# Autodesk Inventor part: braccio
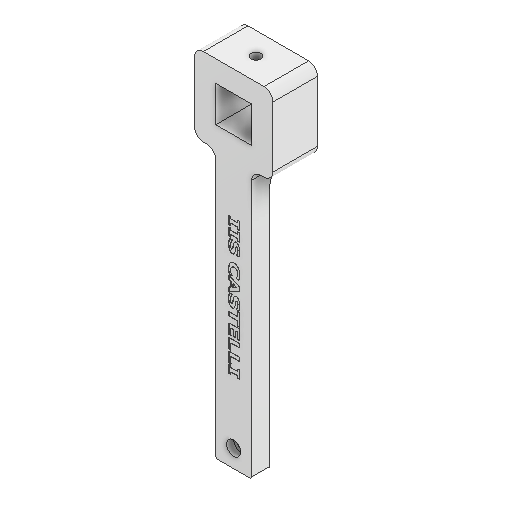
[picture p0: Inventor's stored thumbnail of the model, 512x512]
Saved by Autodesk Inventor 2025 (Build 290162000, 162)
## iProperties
Created: 2025-09
Part Number: braccio
Material: Plastica ABS
Document SubType Name: Modeling
Designer: Ryzen5700u
Density: 1.06 g/cm^3
Appearance: Liscia - Bianco
Author: Ryzen5700u
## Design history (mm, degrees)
sketch "Schizzo1"
  geometry: L1 (-10.05, -10.05)-(10.05, -10.05); L2 (10.05, -10.05)-(10.05, 10.05); L3 (10.05, 10.05)-(-10.05, 10.05); L4 (-10.05, 10.05)-(-10.05, -10.05); L5 (-10.05, -10.05)-(10.05, 10.05); L6 (10.05, -10.05)-(-10.05, 10.05); L7 (-22, -22)-(22, -22); L8 (22, -22)-(22, 22); L9 (22, 22)-(-22, 22); L10 (-22, 22)-(-22, -22); L11 (-22, -22)-(22, 22); L12 (22, -22)-(-22, 22); L13 (-10, -22)-(10, -22); L14 (10, -22)-(10, -172); L15 (10, -172)-(-10, -172); L16 (-10, -172)-(-10, -22); 2 further points
  constraints: 32 end point, 6 parallel, 4 midpoint, 3 horizontal, 3 perpendicular, 1 point on line
  dimensions: "d0" = 20.1 distance of L3.end L2.end; "d1" = 20.1 distance of L2.end L1.end; "d2" = 44 distance of L9.end L8.end; "d3" = 44 distance of L7.end L8.end; "d4" = 150 distance of L13.end L14.end
extrude "Estrusione1" new body sketch "Schizzo1" distance "d5" = 10; taper "d6" = 0 deg
sketch "Schizzo2"
  geometry: L1 (22, -22)-(10, -22) reference; L2 (22, 22)-(22, -22) reference; L3 (-22, 22)-(22, 22) reference; L4 (-22, -22)-(-22, 22) reference; L5 (-10, -22)-(-22, -22) reference; L6 (-10, -172)-(-10, -22) reference; L7 (10, -172)-(-10, -172) reference; L8 (10, -22)-(10, -172) reference; L9 (10.05, -10.05)-(10.05, 10.05) reference; L10 (-10.05, -10.05)-(10.05, -10.05) reference; L11 (-10.05, 10.05)-(-10.05, -10.05) reference; L12 (10.05, 10.05)-(-10.05, 10.05) reference; L13 (10, -22)-(-10, -22); 1 further point
  constraints: 2 end point, 1 horizontal
extrude "Estrusione2" join sketch "Schizzo2" distance "d7" = 15; taper "d8" = 0 deg
sketch "Schizzo3"
  geometry: L1 (44, 25)-(44, 0) reference; L2 (44, 25)-(0, 25) reference; L3 (44, 0)-(0, 25); L4 (0, 0)-(0, 25) reference; L5 (0, 25)-(0, 0); L6 (0, 0)-(44, 25); 2 further points
  constraints: 6 end point, 2 midpoint, 1 collinear
hole "Foro1" sketch "Schizzo3" at (22, 12.5) diameter "d9" = 5.5; stored, may be unused: countersink angle "d13" = 90 deg, drill point angle "d15" = 118 deg; dims "d10" = 6, "d11" = 10, "d12" = 5.7, "d14" = 64.25
fillet "Raccordo1" dims "d16" = 5
sketch "Schizzo4"
  geometry: L1 (4.5, -162)-(2.25, -165.897); L2 (2.25, -165.897)-(-2.25, -165.897); L3 (-2.25, -165.897)-(-4.5, -162); L4 (-4.5, -162)-(-2.25, -158.103); L5 (-2.25, -158.103)-(2.25, -158.103); L6 (2.25, -158.103)-(4.5, -162); C1 r 4 at (0, -162) reference; 2 further points
  constraints: 12 end point, 1 coincident, 13 other
  dimensions: "d21" = 4.5 distance of L4.end L5.end
extrude "Estrusione3" cut sketch "Schizzo4" distance "d17" = 4; taper "d18" = 0 deg
sketch "Schizzo5"
  geometry: C1 r 2.25 at (0, -162) reference; 1 further point
extrude "Estrusione4" cut sketch "Schizzo5" extent not by distance; stored distance "d19" = 4; taper "d20" = 0 deg
sketch "Schizzo6"
  geometry: L1 (3.332, -49.867)-(3.332, -144.876); L2 (3.332, -144.876)-(-4.284, -144.876); L3 (-4.284, -144.876)-(-4.284, -49.867); L4 (-4.284, -49.867)-(3.332, -49.867); 1 further point
  constraints: 2 other
extrude "Estrusione5" cut sketch "Schizzo6" distance "d23" = 0.2; taper "d24" = 0 deg
fillet "Raccordo3" dims "d25" = 15
fillet "Raccordo4" dims "d26" = 1
node "Solido1"
node "Linea chiusa proiettata1"
node "Riferimento1"
node "Riferimento2"
